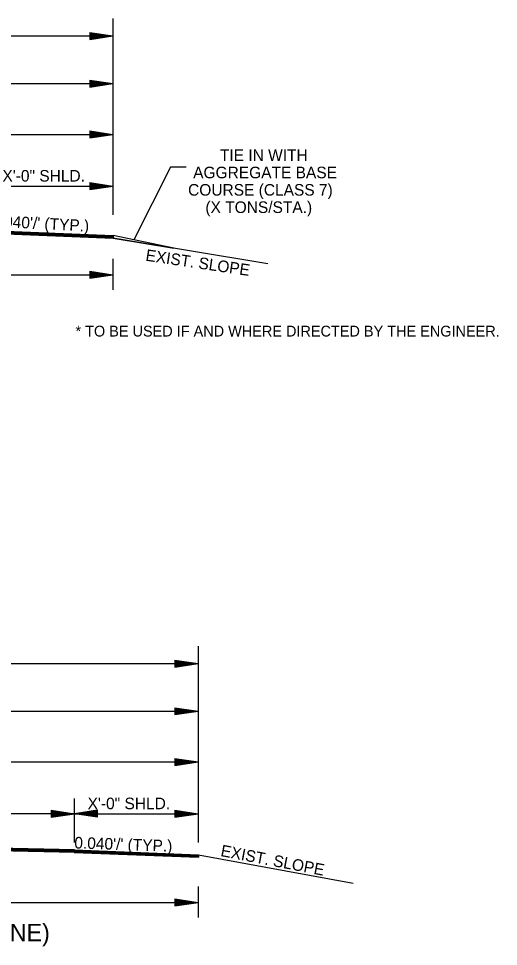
# Model space of a CAD drawing. Extents: x 544199 to 1930787, y -1968972 to 596640.
# Drawn here: x 552096 to 552406, y -1961148 to -1960547 of the extents above; entities that cross this region are included whole.
import ezdxf

# ---------------------------------------------------------------- set-up
doc = ezdxf.new("R2010")
doc.units = 0
doc.layers.add('R_Border Prem', color=7, linetype='Continuous')
doc.layers.add('R_Draft', color=7, linetype='Continuous')

msp = doc.modelspace()

# ---------------------------------------------------------------- linework, layer by layer
at = {"layer": 'R_Draft'}
for p, q in [((552141.84, -1960555.6), (552156.84, -1960557.85)), ((552141.84, -1960555.6), (552141.84, -1960560.1)), ((551636.39, -1960557.85), (552156.84, -1960557.85)), ((552141.84, -1960555.97), (552154.33, -1960557.85)), ((552141.84, -1960556.36), (552151.75, -1960557.85)), ((552141.84, -1960556.73), (552149.25, -1960557.85)), ((552141.84, -1960557.12), (552146.71, -1960557.85)), ((552141.84, -1960557.5), (552144.21, -1960557.85)), ((552141.84, -1960560.1), (552156.84, -1960557.85)), ((552141.84, -1960558.58), (552146.71, -1960557.85)), ((552141.84, -1960559.34), (552151.75, -1960557.85)), ((552141.84, -1960559.72), (552154.33, -1960557.85)), ((552141.84, -1960558.97), (552149.25, -1960557.85)), ((552141.84, -1960558.2), (552144.21, -1960557.85)), ((551636.39, -1960588.72), (552156.84, -1960588.72)), ((552141.84, -1960586.47), (552156.84, -1960588.72)), ((552141.84, -1960586.47), (552141.84, -1960590.97)), ((552141.84, -1960586.84), (552154.33, -1960588.72)), ((552141.84, -1960587.23), (552151.75, -1960588.72)), ((552141.84, -1960587.6), (552149.25, -1960588.72)), ((552141.84, -1960587.99), (552146.71, -1960588.72)), ((552141.84, -1960588.37), (552144.21, -1960588.72)), ((552141.84, -1960590.97), (552156.84, -1960588.72)), ((552141.84, -1960589.45), (552146.71, -1960588.72)), ((552141.84, -1960590.21), (552151.75, -1960588.72)), ((552141.84, -1960590.59), (552154.33, -1960588.72)), ((552141.84, -1960589.84), (552149.25, -1960588.72)), ((552141.84, -1960589.07), (552144.21, -1960588.72)), ((551636.39, -1960621.65), (552156.84, -1960621.65)), ((552141.84, -1960619.4), (552156.84, -1960621.65)), ((552141.84, -1960619.4), (552141.84, -1960623.9)), ((552141.84, -1960619.77), (552154.33, -1960621.65)), ((552141.84, -1960620.16), (552151.75, -1960621.65)), ((552141.84, -1960620.53), (552149.25, -1960621.65)), ((552141.84, -1960620.92), (552146.71, -1960621.65)), ((552141.84, -1960621.3), (552144.21, -1960621.65)), ((552141.84, -1960623.9), (552156.84, -1960621.65)), ((552141.84, -1960622.38), (552146.71, -1960621.65)), ((552141.84, -1960623.14), (552151.75, -1960621.65)), ((552141.84, -1960623.52), (552154.33, -1960621.65)), ((552141.84, -1960622.77), (552149.25, -1960621.65)), ((552141.84, -1960622), (552144.21, -1960621.65)), ((552076.84, -1960655.19), (552156.84, -1960655.19)), ((552141.84, -1960652.94), (552156.84, -1960655.19)), ((552141.84, -1960652.94), (552141.84, -1960657.44)), ((552141.84, -1960653.31), (552154.33, -1960655.19)), ((552141.84, -1960653.69), (552151.75, -1960655.19)), ((552141.84, -1960654.07), (552149.25, -1960655.19)), ((552141.84, -1960654.46), (552146.71, -1960655.19)), ((552141.84, -1960654.83), (552144.21, -1960655.19)), ((552141.84, -1960657.44), (552156.84, -1960655.19)), ((552141.84, -1960655.92), (552146.71, -1960655.19)), ((552141.84, -1960656.68), (552151.75, -1960655.19)), ((552141.84, -1960657.06), (552154.33, -1960655.19)), ((552141.84, -1960656.3), (552149.25, -1960655.19)), ((552141.84, -1960655.54), (552144.21, -1960655.19)), ((552076.77, -1960685.7), (552157.11, -1960688.91)), ((552076.78, -1960685.5), (552157.1, -1960688.71)), ((552076.79, -1960685.2), (552157.1, -1960688.41)), ((552076.8, -1960684.9), (552157.1, -1960688.11)), ((552076.81, -1960684.6), (552157.1, -1960687.81)), ((552076.82, -1960684.3), (552157.1, -1960687.51)), ((552076.84, -1960684), (552157.1, -1960687.21)), ((552157.1, -1960687.21), (552157.1, -1960688.91)), ((552196.34, -1960695.45), (552157.1, -1960687.21)), ((552157.1, -1960687.21), (552157.1, -1960688.91)), ((552257.17, -1960705.59), (552157.1, -1960688.91)), ((552157.1, -1960688.91), (552157.1, -1960688.91)), ((552157.1, -1960688.91), (552196.34, -1960695.45)), ((552156.84, -1960702.4), (552156.84, -1960722.4)), ((552141.84, -1960710.4), (552156.84, -1960712.65)), ((552141.84, -1960710.4), (552141.84, -1960714.9)), ((552141.84, -1960710.78), (552154.33, -1960712.65)), ((552141.84, -1960711.16), (552151.75, -1960712.65)), ((552141.84, -1960711.53), (552149.25, -1960712.65)), ((552141.84, -1960711.92), (552146.71, -1960712.65)), ((551636.39, -1960712.65), (552156.84, -1960712.65)), ((552141.84, -1960712.3), (552144.21, -1960712.65)), ((552141.84, -1960714.9), (552156.84, -1960712.65)), ((552141.84, -1960713.39), (552146.71, -1960712.65)), ((552141.84, -1960714.14), (552151.75, -1960712.65)), ((552141.84, -1960714.53), (552154.33, -1960712.65)), ((552141.84, -1960713.77), (552149.25, -1960712.65)), ((552141.84, -1960713), (552144.21, -1960712.65)), ((551691.52, -1960964.67), (552211.97, -1960964.67)), ((552196.97, -1960962.42), (552211.97, -1960964.67)), ((552196.97, -1960962.42), (552196.97, -1960966.92)), ((552196.97, -1960962.8), (552209.47, -1960964.67)), ((552196.97, -1960963.18), (552206.89, -1960964.67)), ((552196.97, -1960963.55), (552204.39, -1960964.67)), ((552196.97, -1960963.94), (552201.85, -1960964.67)), ((552196.97, -1960964.32), (552199.34, -1960964.67)), ((552196.97, -1960966.92), (552211.97, -1960964.67)), ((552196.97, -1960965.41), (552201.85, -1960964.67)), ((552196.97, -1960966.16), (552206.89, -1960964.67)), ((552196.97, -1960966.55), (552209.47, -1960964.67)), ((552196.97, -1960965.79), (552204.39, -1960964.67)), ((552196.97, -1960965.02), (552199.34, -1960964.67)), ((552196.97, -1960993.29), (552211.97, -1960995.54)), ((552196.97, -1960993.29), (552196.97, -1960997.79)), ((552196.97, -1960993.67), (552209.47, -1960995.54)), ((552196.97, -1960994.05), (552206.89, -1960995.54)), ((552196.97, -1960994.42), (552204.39, -1960995.54)), ((552196.97, -1960994.81), (552201.85, -1960995.54)), ((551691.52, -1960995.54), (552211.97, -1960995.54)), ((552196.97, -1960995.19), (552199.34, -1960995.54)), ((552196.97, -1960997.79), (552211.97, -1960995.54)), ((552196.97, -1960996.28), (552201.85, -1960995.54)), ((552196.97, -1960997.03), (552206.89, -1960995.54)), ((552196.97, -1960997.42), (552209.47, -1960995.54)), ((552196.97, -1960996.66), (552204.39, -1960995.54)), ((552196.97, -1960995.89), (552199.34, -1960995.54)), ((551691.52, -1961028.47), (552211.97, -1961028.47)), ((552196.97, -1961026.22), (552211.97, -1961028.47)), ((552196.97, -1961026.22), (552196.97, -1961030.72)), ((552196.97, -1961026.6), (552209.47, -1961028.47)), ((552196.97, -1961026.98), (552206.89, -1961028.47)), ((552196.97, -1961027.35), (552204.39, -1961028.47)), ((552196.97, -1961027.74), (552201.85, -1961028.47)), ((552196.97, -1961028.12), (552199.34, -1961028.47)), ((552196.97, -1961030.72), (552211.97, -1961028.47)), ((552196.97, -1961029.21), (552201.85, -1961028.47)), ((552196.97, -1961029.96), (552206.89, -1961028.47)), ((552196.97, -1961030.35), (552209.47, -1961028.47)), ((552196.97, -1961029.59), (552204.39, -1961028.47)), ((552196.97, -1961028.82), (552199.34, -1961028.47)), ((552131.97, -1961080.66), (552131.97, -1961052.11)), ((552116.97, -1961059.76), (552131.97, -1961062.01)), ((552116.97, -1961059.76), (552116.97, -1961064.26)), ((552116.97, -1961060.13), (552129.47, -1961062.01)), ((552116.97, -1961060.51), (552126.89, -1961062.01)), ((552116.97, -1961060.89), (552124.39, -1961062.01)), ((552146.97, -1961059.76), (552131.97, -1961062.01)), ((552146.97, -1961060.13), (552134.48, -1961062.01)), ((552146.97, -1961060.51), (552137.06, -1961062.01)), ((552146.97, -1961060.89), (552139.55, -1961062.01)), ((552146.97, -1961064.26), (552146.97, -1961059.76)), ((552196.97, -1961059.76), (552211.97, -1961062.01)), ((552196.97, -1961059.76), (552196.97, -1961064.26)), ((552196.97, -1961060.13), (552209.47, -1961062.01)), ((552196.97, -1961060.51), (552206.89, -1961062.01)), ((552196.97, -1961060.89), (552204.39, -1961062.01)), ((552131.97, -1961062.01), (552011.71, -1961062.01)), ((552116.97, -1961061.28), (552121.85, -1961062.01)), ((552116.97, -1961061.65), (552119.34, -1961062.01)), ((552116.97, -1961064.26), (552131.97, -1961062.01)), ((552116.97, -1961062.74), (552121.85, -1961062.01)), ((552116.97, -1961063.5), (552126.89, -1961062.01)), ((552116.97, -1961063.88), (552129.47, -1961062.01)), ((552116.97, -1961063.12), (552124.39, -1961062.01)), ((552116.97, -1961062.36), (552119.34, -1961062.01)), ((552131.97, -1961062.01), (552211.97, -1961062.01)), ((552146.97, -1961064.26), (552131.97, -1961062.01)), ((552146.97, -1961063.88), (552134.48, -1961062.01)), ((552146.97, -1961063.5), (552137.06, -1961062.01)), ((552146.97, -1961063.12), (552139.55, -1961062.01)), ((552146.97, -1961061.27), (552142.1, -1961062.01)), ((552146.97, -1961062.73), (552142.1, -1961062.01)), ((552146.97, -1961061.65), (552144.6, -1961062.01)), ((552146.97, -1961062.36), (552144.6, -1961062.01)), ((552196.97, -1961061.28), (552201.85, -1961062.01)), ((552196.97, -1961061.65), (552199.34, -1961062.01)), ((552196.97, -1961064.26), (552211.97, -1961062.01)), ((552196.97, -1961062.74), (552201.85, -1961062.01)), ((552196.97, -1961063.5), (552206.89, -1961062.01)), ((552196.97, -1961063.88), (552209.47, -1961062.01)), ((552196.97, -1961063.12), (552204.39, -1961062.01)), ((552196.97, -1961062.36), (552199.34, -1961062.01)), ((552131.97, -1961085.35), (552011.71, -1961082.95)), ((552131.97, -1961085.65), (552011.71, -1961083.25)), ((552131.96, -1961085.95), (552011.71, -1961083.55)), ((552131.95, -1961086.25), (552011.71, -1961083.85)), ((552131.95, -1961086.55), (552011.71, -1961084.15)), ((552131.94, -1961086.85), (552011.71, -1961084.45)), ((552131.94, -1961087.05), (552011.71, -1961084.65)), ((552131.9, -1961087.05), (552212.24, -1961090.26)), ((552131.91, -1961086.85), (552212.23, -1961090.06)), ((552131.92, -1961086.55), (552212.23, -1961089.76)), ((552131.94, -1961086.25), (552212.23, -1961089.46)), ((552131.95, -1961085.95), (552212.23, -1961089.16)), ((552131.96, -1961085.65), (552212.23, -1961088.86)), ((552131.97, -1961085.35), (552212.23, -1961088.56)), ((552212.23, -1961088.56), (552212.23, -1961090.26)), ((552212.23, -1961088.56), (552212.23, -1961090.26)), ((552212.23, -1961088.56), (552312.3, -1961106.94)), ((552211.97, -1961109.22), (552211.97, -1961129.22)), ((551691.52, -1961119.47), (552211.97, -1961119.47)), ((552196.97, -1961117.22), (552211.97, -1961119.47)), ((552196.97, -1961117.22), (552196.97, -1961121.72)), ((552196.97, -1961117.6), (552209.47, -1961119.47)), ((552196.97, -1961117.98), (552206.89, -1961119.47)), ((552196.97, -1961118.35), (552204.39, -1961119.47)), ((552196.97, -1961118.74), (552201.85, -1961119.47)), ((552196.97, -1961119.12), (552199.34, -1961119.47)), ((552196.97, -1961121.72), (552211.97, -1961119.47)), ((552196.97, -1961120.21), (552201.85, -1961119.47)), ((552196.97, -1961120.96), (552206.89, -1961119.47)), ((552196.97, -1961121.35), (552209.47, -1961119.47)), ((552196.97, -1961120.59), (552204.39, -1961119.47)), ((552196.97, -1961119.82), (552199.34, -1961119.47))]:
    msp.add_line(p, q, dxfattribs=at)
for points in [[(552156.84, -1960546.59), (552156.84, -1960673.84)], [(552204.19, -1960642.97), (552194.19, -1960642.97), (552170.52, -1960690.03)], [(552211.97, -1960953.41), (552211.97, -1961080.66)]]:
    msp.add_lwpolyline(points, dxfattribs=at)

# ---------------------------------------------------------------- texts
at = {"layer": 'R_Border Prem'}
msp.add_text('* TO BE USED IF AND WHERE DIRECTED BY THE ENGINEER.', height=7, dxfattribs=at).set_placement((552132.65, -1960752.7))
at = {"layer": 'R_Draft'}
for s, height, p in [('TIE IN WITH ', 7.5, (552226.14, -1960638.87)), ('X\'-0" SHLD.', 7.5, (552085.36, -1960652.27)), ('AGGREGATE BASE', 7.5, (552208.83, -1960650.12)), ('COURSE (CLASS 7)', 7.5, (552205.53, -1960661.37)), ('(X TONS/STA.)', 7.5, (552216.75, -1960672.62)), ('X\'-0" SHLD.', 7.5, (552140.5, -1961059.09)), ('3 LANE OPEN SHOULDER (WESTBOUND PASSING LANE)', 11.25, (551703.07, -1961144.65))]:
    msp.add_text(s, height=height, dxfattribs=at).set_placement(p)
for s, rotation, p in [("0.040'/' (TYP.)", 356.93347, (552077.93, -1960681.35)), ('EXIST. SLOPE', 351.57554, (552177.69, -1960703.5)), ("0.040'/' (TYP.)", 358.01958, (552131.8, -1961084.47)), ('EXIST. SLOPE', 349.11714, (552226.21, -1961089.39))]:
    msp.add_text(s, height=7.5, rotation=rotation, dxfattribs=at).set_placement(p)

doc.saveas('drawing.dxf')
